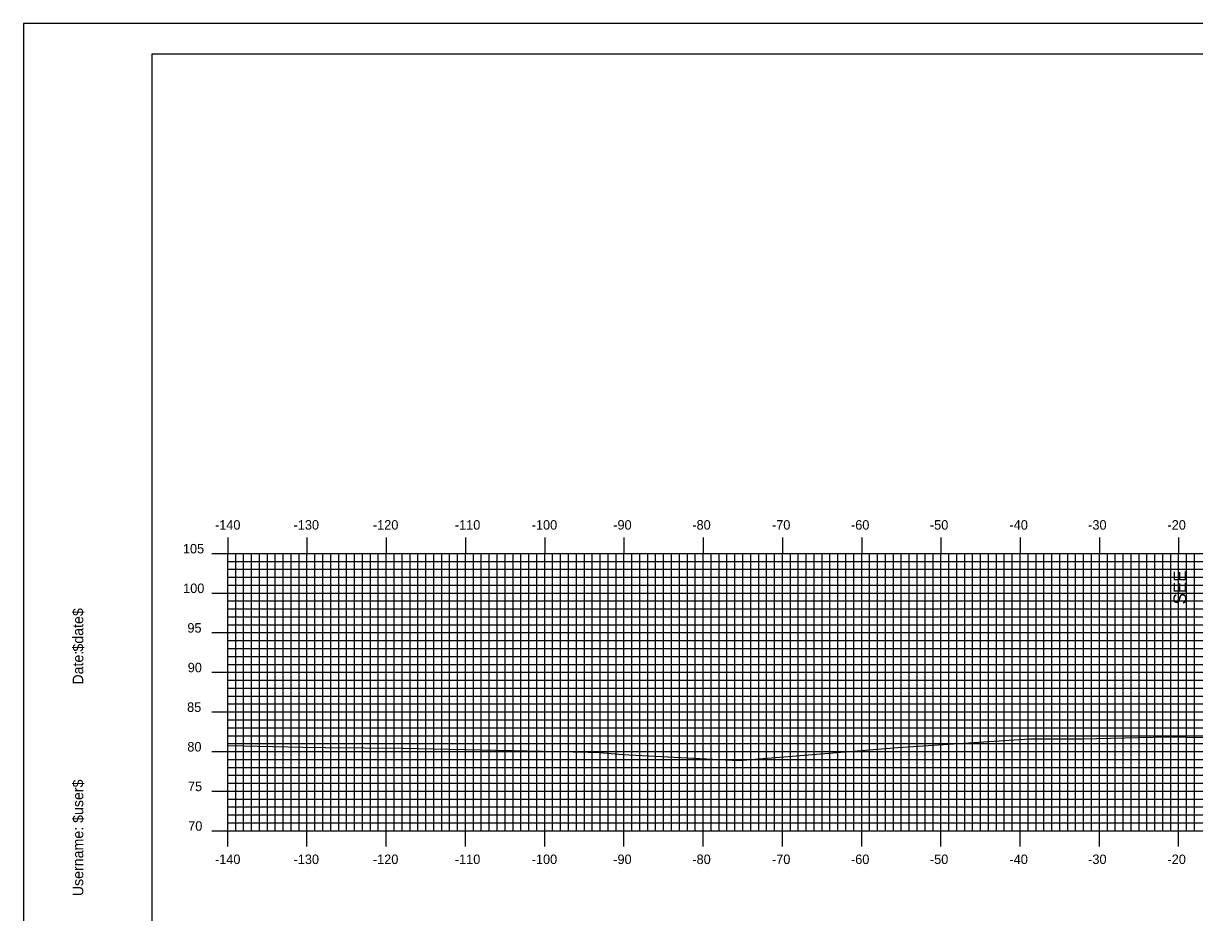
# Model space of a CAD drawing. Extents: x 856716 to 857060, y 364765 to 364985.
# Drawn here: x 856716.5 to 856864.3, y 364873 to 364985.2 of the extents above; entities that cross this region are included whole.
import ezdxf

# ---------------------------------------------------------------- set-up
doc = ezdxf.new("R2010")
doc.units = 0
for name, color, linetype in [('ANNOTATION', 7, 'Continuous'), ('BORDER', 7, 'Continuous'), ('H_V ANNOTATION', 7, 'Continuous'), ('MAJOR', 7, 'Continuous'), ('MINOR', 7, 'Continuous'), ('PLOT BOUNDARY', 7, 'Continuous'), ('S_Roadway_Centerline', 7, 'Continuous')]:
    doc.layers.add(name, color=color, linetype=linetype)

msp = doc.modelspace()

# ---------------------------------------------------------------- linework, layer by layer
at = {"layer": 'BORDER'}
msp.add_lwpolyline([(856732.68, 364771.3), (857052.68, 364771.3), (857052.68, 364981.3), (856732.68, 364981.3)], close=True, dxfattribs=at)
at = {"layer": 'MAJOR'}
for p, q in [((856742.28, 364920.31), (856742.28, 364918.3)), ((856752.28, 364920.31), (856752.28, 364918.3)), ((856762.28, 364920.31), (856762.28, 364918.3)), ((856772.28, 364920.31), (856772.28, 364918.3)), ((856782.28, 364920.31), (856782.28, 364918.3)), ((856792.28, 364920.31), (856792.28, 364918.3)), ((856802.28, 364920.31), (856802.28, 364918.3)), ((856812.28, 364920.31), (856812.28, 364918.3)), ((856822.28, 364920.31), (856822.28, 364918.3)), ((856832.28, 364920.31), (856832.28, 364918.3)), ((856842.28, 364920.31), (856842.28, 364918.3)), ((856852.28, 364920.31), (856852.28, 364918.3)), ((856862.28, 364920.31), (856862.28, 364918.3)), ((856740.28, 364918.3), (856742.28, 364918.3)), ((856742.28, 364918.3), (857022.28, 364918.3)), ((856742.28, 364883.3), (856742.28, 364918.3)), ((856742.28, 364883.3), (856742.28, 364918.3)), ((856742.28, 364918.3), (857022.28, 364918.3)), ((856752.28, 364883.3), (856752.28, 364918.3)), ((856762.28, 364883.3), (856762.28, 364918.3)), ((856772.28, 364883.3), (856772.28, 364918.3)), ((856782.28, 364883.3), (856782.28, 364918.3)), ((856792.28, 364883.3), (856792.28, 364918.3)), ((856802.28, 364883.3), (856802.28, 364918.3)), ((856812.28, 364883.3), (856812.28, 364918.3)), ((856822.28, 364883.3), (856822.28, 364918.3)), ((856832.28, 364883.3), (856832.28, 364918.3)), ((856842.28, 364883.3), (856842.28, 364918.3)), ((856852.28, 364883.3), (856852.28, 364918.3)), ((856862.28, 364883.3), (856862.28, 364918.3)), ((856740.28, 364913.3), (856742.28, 364913.3)), ((856742.28, 364913.3), (857022.28, 364913.3)), ((856740.28, 364908.3), (856742.28, 364908.3)), ((856742.28, 364908.3), (857022.28, 364908.3)), ((856740.28, 364903.3), (856742.28, 364903.3)), ((856742.28, 364903.3), (857022.28, 364903.3)), ((856740.28, 364898.3), (856742.28, 364898.3)), ((856742.28, 364898.3), (857022.28, 364898.3)), ((856740.28, 364893.3), (856742.28, 364893.3)), ((856742.28, 364893.3), (857022.28, 364893.3)), ((856740.28, 364888.3), (856742.28, 364888.3)), ((856742.28, 364888.3), (857022.28, 364888.3)), ((856740.28, 364883.3), (856742.28, 364883.3)), ((856742.28, 364883.3), (857022.28, 364883.3)), ((856742.28, 364883.3), (857022.28, 364883.3)), ((856742.28, 364881.3), (856742.28, 364883.3)), ((856752.28, 364881.3), (856752.28, 364883.3)), ((856762.28, 364881.3), (856762.28, 364883.3)), ((856772.28, 364881.3), (856772.28, 364883.3)), ((856782.28, 364881.3), (856782.28, 364883.3)), ((856792.28, 364881.3), (856792.28, 364883.3)), ((856802.28, 364881.3), (856802.28, 364883.3)), ((856812.28, 364881.3), (856812.28, 364883.3)), ((856822.28, 364881.3), (856822.28, 364883.3)), ((856832.28, 364881.3), (856832.28, 364883.3)), ((856842.28, 364881.3), (856842.28, 364883.3)), ((856852.28, 364881.3), (856852.28, 364883.3)), ((856862.28, 364881.3), (856862.28, 364883.3))]:
    msp.add_line(p, q, dxfattribs=at)
at = {"layer": 'MINOR'}
for p, q in [((856743.28, 364883.3), (856743.28, 364918.3)), ((856744.28, 364883.3), (856744.28, 364918.3)), ((856745.28, 364883.3), (856745.28, 364918.3)), ((856746.28, 364883.3), (856746.28, 364918.3)), ((856747.28, 364883.3), (856747.28, 364918.3)), ((856748.28, 364883.3), (856748.28, 364918.3)), ((856749.28, 364883.3), (856749.28, 364918.3)), ((856750.28, 364883.3), (856750.28, 364918.3)), ((856751.28, 364883.3), (856751.28, 364918.3)), ((856753.28, 364883.3), (856753.28, 364918.3)), ((856754.28, 364883.3), (856754.28, 364918.3)), ((856755.28, 364883.3), (856755.28, 364918.3)), ((856756.28, 364883.3), (856756.28, 364918.3)), ((856757.28, 364883.3), (856757.28, 364918.3)), ((856758.28, 364883.3), (856758.28, 364918.3)), ((856759.28, 364883.3), (856759.28, 364918.3)), ((856760.28, 364883.3), (856760.28, 364918.3)), ((856761.28, 364883.3), (856761.28, 364918.3)), ((856763.28, 364883.3), (856763.28, 364918.3)), ((856764.28, 364883.3), (856764.28, 364918.3)), ((856765.28, 364883.3), (856765.28, 364918.3)), ((856766.28, 364883.3), (856766.28, 364918.3)), ((856767.28, 364883.3), (856767.28, 364918.3)), ((856768.28, 364883.3), (856768.28, 364918.3)), ((856769.28, 364883.3), (856769.28, 364918.3)), ((856770.28, 364883.3), (856770.28, 364918.3)), ((856771.28, 364883.3), (856771.28, 364918.3)), ((856773.28, 364883.3), (856773.28, 364918.3)), ((856774.28, 364883.3), (856774.28, 364918.3)), ((856775.28, 364883.3), (856775.28, 364918.3)), ((856776.28, 364883.3), (856776.28, 364918.3)), ((856777.28, 364883.3), (856777.28, 364918.3)), ((856778.28, 364883.3), (856778.28, 364918.3)), ((856779.28, 364883.3), (856779.28, 364918.3)), ((856780.28, 364883.3), (856780.28, 364918.3)), ((856781.28, 364883.3), (856781.28, 364918.3)), ((856783.28, 364883.3), (856783.28, 364918.3)), ((856784.28, 364883.3), (856784.28, 364918.3)), ((856785.28, 364883.3), (856785.28, 364918.3)), ((856786.28, 364883.3), (856786.28, 364918.3)), ((856787.28, 364883.3), (856787.28, 364918.3)), ((856788.28, 364883.3), (856788.28, 364918.3)), ((856789.28, 364883.3), (856789.28, 364918.3)), ((856790.28, 364883.3), (856790.28, 364918.3)), ((856791.28, 364883.3), (856791.28, 364918.3)), ((856793.28, 364883.3), (856793.28, 364918.3)), ((856794.28, 364883.3), (856794.28, 364918.3)), ((856795.28, 364883.3), (856795.28, 364918.3)), ((856796.28, 364883.3), (856796.28, 364918.3)), ((856797.28, 364883.3), (856797.28, 364918.3)), ((856798.28, 364883.3), (856798.28, 364918.3)), ((856799.28, 364883.3), (856799.28, 364918.3)), ((856800.28, 364883.3), (856800.28, 364918.3)), ((856801.28, 364883.3), (856801.28, 364918.3)), ((856803.28, 364883.3), (856803.28, 364918.3)), ((856804.28, 364883.3), (856804.28, 364918.3)), ((856805.28, 364883.3), (856805.28, 364918.3)), ((856806.28, 364883.3), (856806.28, 364918.3)), ((856807.28, 364883.3), (856807.28, 364918.3)), ((856808.28, 364883.3), (856808.28, 364918.3)), ((856809.28, 364883.3), (856809.28, 364918.3)), ((856810.28, 364883.3), (856810.28, 364918.3)), ((856811.28, 364883.3), (856811.28, 364918.3)), ((856813.28, 364883.3), (856813.28, 364918.3)), ((856814.28, 364883.3), (856814.28, 364918.3)), ((856815.28, 364883.3), (856815.28, 364918.3)), ((856816.28, 364883.3), (856816.28, 364918.3)), ((856817.28, 364883.3), (856817.28, 364918.3)), ((856818.28, 364883.3), (856818.28, 364918.3)), ((856819.28, 364883.3), (856819.28, 364918.3)), ((856820.28, 364883.3), (856820.28, 364918.3)), ((856821.28, 364883.3), (856821.28, 364918.3)), ((856823.28, 364883.3), (856823.28, 364918.3)), ((856824.28, 364883.3), (856824.28, 364918.3)), ((856825.28, 364883.3), (856825.28, 364918.3)), ((856826.28, 364883.3), (856826.28, 364918.3)), ((856827.28, 364883.3), (856827.28, 364918.3)), ((856828.28, 364883.3), (856828.28, 364918.3)), ((856829.28, 364883.3), (856829.28, 364918.3)), ((856830.28, 364883.3), (856830.28, 364918.3)), ((856831.28, 364883.3), (856831.28, 364918.3)), ((856833.28, 364883.3), (856833.28, 364918.3)), ((856834.28, 364883.3), (856834.28, 364918.3)), ((856835.28, 364883.3), (856835.28, 364918.3)), ((856836.28, 364883.3), (856836.28, 364918.3)), ((856837.28, 364883.3), (856837.28, 364918.3)), ((856838.28, 364883.3), (856838.28, 364918.3)), ((856839.28, 364883.3), (856839.28, 364918.3)), ((856840.28, 364883.3), (856840.28, 364918.3)), ((856841.28, 364883.3), (856841.28, 364918.3)), ((856843.28, 364883.3), (856843.28, 364918.3)), ((856844.28, 364883.3), (856844.28, 364918.3)), ((856845.28, 364883.3), (856845.28, 364918.3)), ((856846.28, 364883.3), (856846.28, 364918.3)), ((856847.28, 364883.3), (856847.28, 364918.3)), ((856848.28, 364883.3), (856848.28, 364918.3)), ((856849.28, 364883.3), (856849.28, 364918.3)), ((856850.28, 364883.3), (856850.28, 364918.3)), ((856851.28, 364883.3), (856851.28, 364918.3)), ((856853.28, 364883.3), (856853.28, 364918.3)), ((856854.28, 364883.3), (856854.28, 364918.3)), ((856855.28, 364883.3), (856855.28, 364918.3)), ((856856.28, 364883.3), (856856.28, 364918.3)), ((856857.28, 364883.3), (856857.28, 364918.3)), ((856858.28, 364883.3), (856858.28, 364918.3)), ((856859.28, 364883.3), (856859.28, 364918.3)), ((856860.28, 364883.3), (856860.28, 364918.3)), ((856861.28, 364883.3), (856861.28, 364918.3)), ((856863.28, 364883.3), (856863.28, 364918.3)), ((856864.28, 364883.3), (856864.28, 364918.3)), ((856742.28, 364917.3), (857022.28, 364917.3)), ((856742.28, 364917.3), (856744.29, 364917.3)), ((856742.28, 364916.3), (857022.28, 364916.3)), ((856742.28, 364916.3), (856744.29, 364916.3)), ((856742.28, 364915.3), (857022.28, 364915.3)), ((856742.28, 364915.3), (856744.29, 364915.3)), ((856742.28, 364914.3), (857022.28, 364914.3)), ((856742.28, 364914.3), (856744.29, 364914.3)), ((856742.28, 364912.3), (857022.28, 364912.3)), ((856742.28, 364912.3), (856744.29, 364912.3)), ((856742.28, 364911.3), (857022.28, 364911.3)), ((856742.28, 364911.3), (856744.29, 364911.3)), ((856742.28, 364910.3), (857022.28, 364910.3)), ((856742.28, 364910.3), (856744.29, 364910.3)), ((856742.28, 364909.3), (857022.28, 364909.3)), ((856742.28, 364909.3), (856744.29, 364909.3)), ((856742.28, 364907.3), (857022.28, 364907.3)), ((856742.28, 364907.3), (856744.29, 364907.3)), ((856742.28, 364906.3), (857022.28, 364906.3)), ((856742.28, 364906.3), (856744.29, 364906.3)), ((856742.28, 364905.3), (857022.28, 364905.3)), ((856742.28, 364905.3), (856744.29, 364905.3)), ((856742.28, 364904.3), (857022.28, 364904.3)), ((856742.28, 364904.3), (856744.29, 364904.3)), ((856742.28, 364902.3), (857022.28, 364902.3)), ((856742.28, 364902.3), (856744.29, 364902.3)), ((856742.28, 364901.3), (857022.28, 364901.3)), ((856742.28, 364901.3), (856744.29, 364901.3)), ((856742.28, 364900.3), (857022.28, 364900.3)), ((856742.28, 364900.3), (856744.29, 364900.3)), ((856742.28, 364899.3), (857022.28, 364899.3)), ((856742.28, 364899.3), (856744.29, 364899.3)), ((856742.28, 364897.3), (857022.28, 364897.3)), ((856742.28, 364897.3), (856744.29, 364897.3)), ((856742.28, 364896.3), (857022.28, 364896.3)), ((856742.28, 364896.3), (856744.29, 364896.3)), ((856742.28, 364895.3), (857022.28, 364895.3)), ((856742.28, 364895.3), (856744.29, 364895.3)), ((856742.28, 364894.3), (857022.28, 364894.3)), ((856742.28, 364894.3), (856744.29, 364894.3)), ((856742.28, 364892.3), (857022.28, 364892.3)), ((856742.28, 364892.3), (856744.29, 364892.3)), ((856742.28, 364891.3), (857022.28, 364891.3)), ((856742.28, 364891.3), (856744.29, 364891.3)), ((856742.28, 364890.3), (857022.28, 364890.3)), ((856742.28, 364890.3), (856744.29, 364890.3)), ((856742.28, 364889.3), (857022.28, 364889.3)), ((856742.28, 364889.3), (856744.29, 364889.3)), ((856742.28, 364887.3), (857022.28, 364887.3)), ((856742.28, 364887.3), (856744.29, 364887.3)), ((856742.28, 364886.3), (857022.28, 364886.3)), ((856742.28, 364886.3), (856744.29, 364886.3)), ((856742.28, 364885.3), (857022.28, 364885.3)), ((856742.28, 364885.3), (856744.29, 364885.3)), ((856742.28, 364884.3), (857022.28, 364884.3)), ((856742.28, 364884.3), (856744.29, 364884.3))]:
    msp.add_line(p, q, dxfattribs=at)
at = {"layer": 'PLOT BOUNDARY'}
msp.add_lwpolyline([(856716.49, 364765.18), (857056.49, 364765.18), (857056.49, 364985.18), (856716.49, 364985.18)], close=True, dxfattribs=at)
at = {"layer": 'S_Roadway_Centerline'}
msp.add_lwpolyline([(856742.28, 364894.08), (856751.76, 364893.86), (856754.6, 364893.8), (856764.43, 364893.74), (856783.93, 364893.32), (856787.75, 364893.2), (856789.21, 364893.16), (856792.12, 364892.92), (856806.73, 364892.16), (856813.51, 364892.7), (856826.86, 364893.81), (856843.45, 364894.9), (856850.09, 364894.89), (856860.89, 364895.16), (856865.56, 364895.05)], dxfattribs=at)

# ---------------------------------------------------------------- texts
at = {"layer": 'ANNOTATION'}
msp.add_text('SEE', height=1.6, rotation=90, dxfattribs=at).set_placement((856863.23, 364911.86))
at = {"layer": 'BORDER'}
for s, p in [('$date$', (856724.05, 364905.91)), ('Date:', (856724.05, 364901.74)), ('$user$', (856724.05, 364884.29)), ('Username:', (856724.05, 364875.04))]:
    msp.add_text(s, height=1.339, rotation=90, dxfattribs=at).set_placement(p)
at = {"layer": 'H_V ANNOTATION'}
for s, p in [('-140', (856740.67, 364921.3)), ('-130', (856750.59, 364921.3)), ('-120', (856760.6, 364921.3)), ('-110', (856770.94, 364921.3)), ('-100', (856780.64, 364921.3)), ('-90', (856790.93, 364921.3)), ('-80', (856800.91, 364921.3)), ('-70', (856810.96, 364921.3)), ('-60', (856820.93, 364921.3)), ('-50', (856830.89, 364921.3)), ('-40', (856840.93, 364921.3)), ('-30', (856850.86, 364921.3)), ('-20', (856860.87, 364921.3)), ('105', (856736.62, 364918.3)), ('100', (856736.65, 364913.3)), ('95', (856737.19, 364908.3)), ('90', (856737.23, 364903.3)), ('85', (856737.15, 364898.3)), ('80', (856737.18, 364893.3)), ('75', (856737.26, 364888.3)), ('70', (856737.29, 364883.3)), ('-140', (856740.67, 364879.1)), ('-130', (856750.59, 364879.1)), ('-120', (856760.6, 364879.1)), ('-110', (856770.94, 364879.1)), ('-100', (856780.64, 364879.1)), ('-90', (856790.93, 364879.1)), ('-80', (856800.91, 364879.1)), ('-70', (856810.96, 364879.1)), ('-60', (856820.93, 364879.1)), ('-50', (856830.89, 364879.1)), ('-40', (856840.93, 364879.1)), ('-30', (856850.86, 364879.1)), ('-20', (856860.87, 364879.1))]:
    msp.add_text(s, height=1.2, dxfattribs=at).set_placement(p)
at = {"layer": 'MAJOR'}
msp.add_text('-', height=0.012, dxfattribs=at).set_placement((856742.27, 364883.3))

doc.saveas('drawing.dxf')
